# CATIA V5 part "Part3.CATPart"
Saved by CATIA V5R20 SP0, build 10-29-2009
Part number: Part3
Bounding box of the stored display mesh (mm): x 0 to 0, y 0.328 to 13.184, z 33.184 to 48.505
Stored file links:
  C:\Documents and Settings\Media\Escritorio\GATO_ALAMBRICO\Part3.CATPart
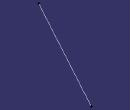
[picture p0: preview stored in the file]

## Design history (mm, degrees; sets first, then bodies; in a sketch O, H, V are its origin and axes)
Set1
  Line1: type Angle, RefPoint Point1, Curve Line2, Support yz-plane, Start 0, End 20, Angle 85
  Line2: stored without definition
  Point1: stored without definition
Body1 (main body)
